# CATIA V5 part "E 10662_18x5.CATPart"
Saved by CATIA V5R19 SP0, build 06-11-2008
Part number: E 10662_18x5
Definition: E 10662_18x5
Nomenclature: E 10662_18x5
Source: Unknown
Description: PART--DESC
Bounding box of the stored display mesh (mm): x 16 to 34, y -9 to 9, z -49.9 to -45
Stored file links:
  C:\Users\jsmid\Desktop\DP_Smidak_Forma LEGO\E 10662_18x5.CATPart
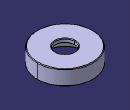
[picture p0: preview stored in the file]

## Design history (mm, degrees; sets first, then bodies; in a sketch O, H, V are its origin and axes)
Body1 "E 10662_18x5" (main body)
  Solid1: solid without history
